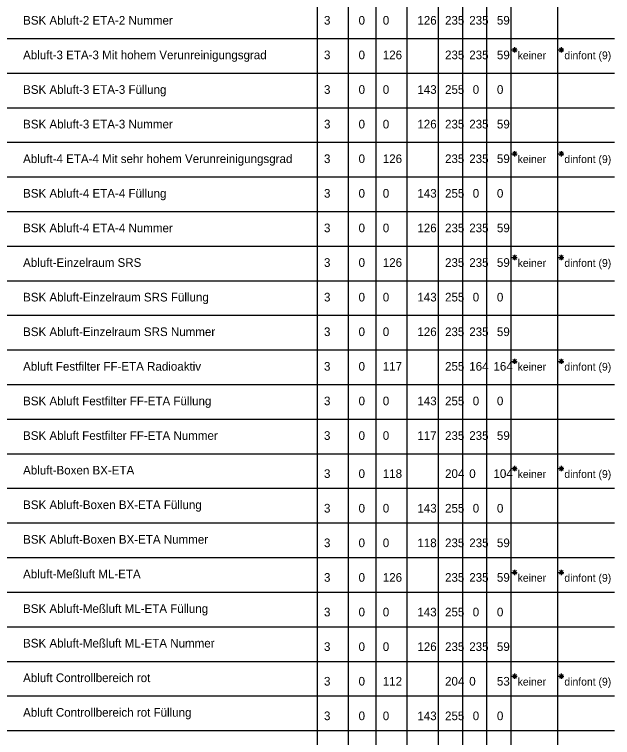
# Model space of a CAD drawing. Extents: x -12.9 to 27.6, y -77.8 to 7.2.
# Drawn here: x 8.13 to 16.77, y -35.1 to -24.65 of the extents above; entities that cross this region are included whole.
import ezdxf

# ---------------------------------------------------------------- set-up
doc = ezdxf.new("R2010")
doc.units = 0
doc.layers.add('Default', color=7, linetype='Continuous')

msp = doc.modelspace()

# ---------------------------------------------------------------- linework, layer by layer
at = {"layer": 'Default'}
for p, q in [((12.5, 0), (12.5, -73.5)), ((12.95, -0.35), (12.95, -59.5)), ((13.35, -0.35), (13.35, -59.5)), ((13.8, -0.35), (13.8, -59.5)), ((14.25, -0.35), (14.25, -59.5)), ((15.3, -0.35), (15.3, -59.5)), ((15.975, -0.35), (15.975, -59.5)), ((14.6, -0.75), (14.6, -59.5)), ((14.95, -0.75), (14.95, -59.5)), ((0, -25), (16.8, -25)), ((15.317, -25.165), (15.393, -25.165)), ((15.328, -25.138), (15.382, -25.192)), ((15.382, -25.138), (15.328, -25.192)), ((15.355, -25.127), (15.355, -25.203)), ((15.992, -25.165), (16.068, -25.165)), ((16.003, -25.138), (16.057, -25.192)), ((16.057, -25.138), (16.003, -25.192)), ((16.03, -25.127), (16.03, -25.203)), ((0, -25.5), (16.8, -25.5)), ((0, -26), (16.8, -26)), ((0, -26.5), (16.8, -26.5)), ((15.328, -26.638), (15.382, -26.692)), ((15.382, -26.638), (15.328, -26.692)), ((15.355, -26.627), (15.355, -26.703)), ((16.003, -26.638), (16.057, -26.692)), ((16.057, -26.638), (16.003, -26.692)), ((16.03, -26.627), (16.03, -26.703)), ((15.317, -26.665), (15.393, -26.665)), ((15.992, -26.665), (16.068, -26.665)), ((0, -27), (16.8, -27)), ((0, -27.5), (16.8, -27.5)), ((0, -28), (16.8, -28)), ((15.317, -28.165), (15.393, -28.165)), ((15.328, -28.138), (15.382, -28.192)), ((15.382, -28.138), (15.328, -28.192)), ((15.355, -28.127), (15.355, -28.203)), ((15.992, -28.165), (16.068, -28.165)), ((16.003, -28.138), (16.057, -28.192)), ((16.057, -28.138), (16.003, -28.192)), ((16.03, -28.127), (16.03, -28.203)), ((0, -28.5), (16.8, -28.5)), ((0, -29), (16.8, -29)), ((0, -29.5), (16.8, -29.5)), ((15.317, -29.665), (15.393, -29.665)), ((15.328, -29.638), (15.382, -29.692)), ((15.382, -29.638), (15.328, -29.692)), ((15.355, -29.627), (15.355, -29.703)), ((15.992, -29.665), (16.068, -29.665)), ((16.003, -29.638), (16.057, -29.692)), ((16.057, -29.638), (16.003, -29.692)), ((16.03, -29.627), (16.03, -29.703)), ((0, -30), (16.8, -30)), ((0, -30.5), (16.8, -30.5)), ((0, -31), (16.8, -31)), ((15.317, -31.215), (15.393, -31.215)), ((15.328, -31.188), (15.382, -31.242)), ((15.382, -31.188), (15.328, -31.242)), ((15.355, -31.177), (15.355, -31.253)), ((15.992, -31.215), (16.068, -31.215)), ((16.003, -31.188), (16.057, -31.242)), ((16.057, -31.188), (16.003, -31.242)), ((16.03, -31.177), (16.03, -31.253)), ((0, -31.5), (16.8, -31.5)), ((0, -32), (16.8, -32)), ((0, -32.5), (16.8, -32.5)), ((15.328, -32.688), (15.382, -32.742)), ((15.382, -32.688), (15.328, -32.742)), ((15.355, -32.677), (15.355, -32.753)), ((16.003, -32.688), (16.057, -32.742)), ((16.057, -32.688), (16.003, -32.742)), ((16.03, -32.677), (16.03, -32.753)), ((15.317, -32.715), (15.393, -32.715)), ((15.992, -32.715), (16.068, -32.715)), ((0, -33), (16.8, -33)), ((0, -33.5), (16.8, -33.5)), ((0, -34.001), (16.8, -34.001)), ((15.317, -34.215), (15.393, -34.215)), ((15.328, -34.188), (15.382, -34.242)), ((15.382, -34.188), (15.328, -34.242)), ((15.355, -34.177), (15.355, -34.253)), ((15.992, -34.215), (16.068, -34.215)), ((16.003, -34.188), (16.057, -34.242)), ((16.057, -34.188), (16.003, -34.242)), ((16.03, -34.177), (16.03, -34.253)), ((0, -34.5), (16.8, -34.5)), ((0, -35), (16.8, -35))]:
    msp.add_line(p, q, dxfattribs=at)

# ---------------------------------------------------------------- texts
for s, height, p in [('BSK Abluft-2 ETA-2 Nummer', 0.125, (8.25, -24.8)), ('3', 0.125, (12.6, -24.8)), ('0', 0.125, (13.1, -24.8)), ('0', 0.125, (13.45, -24.8)), ('126', 0.125, (13.95, -24.8)), ('235', 0.125, (14.35, -24.8)), ('235', 0.125, (14.7, -24.8)), ('59', 0.125, (15.1, -24.8)), ('Abluft-3 ETA-3 Mit hohem Verunreinigungsgrad', 0.125, (8.25, -25.3)), ('3', 0.125, (12.6, -25.3)), ('0', 0.125, (13.1, -25.3)), ('126', 0.125, (13.45, -25.3)), ('235', 0.125, (14.35, -25.3)), ('235', 0.125, (14.7, -25.3)), ('59', 0.125, (15.1, -25.3)), ('keiner', 0.1125, (15.4, -25.3)), ('dinfont (9)', 0.1125, (16.075, -25.3)), ('BSK Abluft-3 ETA-3 Füllung', 0.125, (8.25, -25.8)), ('3', 0.125, (12.6, -25.8)), ('0', 0.125, (13.1, -25.8)), ('0', 0.125, (13.45, -25.8)), ('143', 0.125, (13.95, -25.8)), ('255', 0.125, (14.35, -25.8)), ('0', 0.125, (14.75, -25.8)), ('0', 0.125, (15.1, -25.8)), ('BSK Abluft-3 ETA-3 Nummer', 0.125, (8.25, -26.3)), ('3', 0.125, (12.6, -26.3)), ('0', 0.125, (13.1, -26.3)), ('0', 0.125, (13.45, -26.3)), ('126', 0.125, (13.95, -26.3)), ('235', 0.125, (14.35, -26.3)), ('235', 0.125, (14.7, -26.3)), ('59', 0.125, (15.1, -26.3)), ('Abluft-4 ETA-4 Mit sehr hohem Verunreinigungsgrad', 0.125, (8.25, -26.8)), ('3', 0.125, (12.6, -26.8)), ('0', 0.125, (13.1, -26.8)), ('126', 0.125, (13.45, -26.8)), ('235', 0.125, (14.35, -26.8)), ('235', 0.125, (14.7, -26.8)), ('59', 0.125, (15.1, -26.8)), ('keiner', 0.1125, (15.4, -26.8)), ('dinfont (9)', 0.1125, (16.075, -26.8)), ('BSK Abluft-4 ETA-4 Füllung', 0.125, (8.25, -27.3)), ('3', 0.125, (12.6, -27.3)), ('0', 0.125, (13.1, -27.3)), ('0', 0.125, (13.45, -27.3)), ('143', 0.125, (13.95, -27.3)), ('255', 0.125, (14.35, -27.3)), ('0', 0.125, (14.75, -27.3)), ('0', 0.125, (15.1, -27.3)), ('BSK Abluft-4 ETA-4 Nummer', 0.125, (8.25, -27.8)), ('3', 0.125, (12.6, -27.8)), ('0', 0.125, (13.1, -27.8)), ('0', 0.125, (13.45, -27.8)), ('126', 0.125, (13.95, -27.8)), ('235', 0.125, (14.35, -27.8)), ('235', 0.125, (14.7, -27.8)), ('59', 0.125, (15.1, -27.8)), ('Abluft-Einzelraum SRS', 0.125, (8.25, -28.3)), ('3', 0.125, (12.6, -28.3)), ('0', 0.125, (13.1, -28.3)), ('126', 0.125, (13.45, -28.3)), ('235', 0.125, (14.35, -28.3)), ('235', 0.125, (14.7, -28.3)), ('59', 0.125, (15.1, -28.3)), ('keiner', 0.1125, (15.4, -28.3)), ('dinfont (9)', 0.1125, (16.075, -28.3)), ('BSK Abluft-Einzelraum SRS Füllung', 0.125, (8.25, -28.8)), ('3', 0.125, (12.6, -28.8)), ('0', 0.125, (13.1, -28.8)), ('0', 0.125, (13.45, -28.8)), ('143', 0.125, (13.95, -28.8)), ('255', 0.125, (14.35, -28.8)), ('0', 0.125, (14.75, -28.8)), ('0', 0.125, (15.1, -28.8)), ('BSK Abluft-Einzelraum SRS Nummer', 0.125, (8.25, -29.3)), ('3', 0.125, (12.6, -29.3)), ('0', 0.125, (13.1, -29.3)), ('0', 0.125, (13.45, -29.3)), ('126', 0.125, (13.95, -29.3)), ('235', 0.125, (14.35, -29.3)), ('235', 0.125, (14.7, -29.3)), ('59', 0.125, (15.1, -29.3)), ('Abluft Festfilter FF-ETA Radioaktiv ', 0.125, (8.25, -29.8)), ('3', 0.125, (12.6, -29.8)), ('0', 0.125, (13.1, -29.8)), ('117', 0.125, (13.45, -29.8)), ('255', 0.125, (14.35, -29.8)), ('164', 0.125, (14.7, -29.8)), ('164', 0.125, (15.05, -29.8)), ('keiner', 0.1125, (15.4, -29.8)), ('dinfont (9)', 0.1125, (16.075, -29.8)), ('BSK Abluft Festfilter FF-ETA Füllung', 0.125, (8.25, -30.3)), ('3', 0.125, (12.6, -30.3)), ('0', 0.125, (13.1, -30.3)), ('0', 0.125, (13.45, -30.3)), ('143', 0.125, (13.95, -30.3)), ('255', 0.125, (14.35, -30.3)), ('0', 0.125, (14.75, -30.3)), ('0', 0.125, (15.1, -30.3)), ('BSK Abluft Festfilter FF-ETA Nummer', 0.125, (8.25, -30.8)), ('3', 0.125, (12.6, -30.8)), ('0', 0.125, (13.1, -30.8)), ('0', 0.125, (13.45, -30.8)), ('117', 0.125, (13.95, -30.8)), ('235', 0.125, (14.35, -30.8)), ('235', 0.125, (14.7, -30.8)), ('59', 0.125, (15.1, -30.8)), ('Abluft-Boxen BX-ETA', 0.125, (8.25, -31.3)), ('3', 0.125, (12.6, -31.35)), ('0', 0.125, (13.1, -31.35)), ('118', 0.125, (13.45, -31.35)), ('204', 0.125, (14.35, -31.35)), ('0', 0.125, (14.7, -31.35)), ('104', 0.125, (15.05, -31.35)), ('keiner', 0.1125, (15.4, -31.35)), ('dinfont (9)', 0.1125, (16.075, -31.35)), ('BSK Abluft-Boxen BX-ETA Füllung', 0.125, (8.25, -31.8)), ('3', 0.125, (12.6, -31.85)), ('0', 0.125, (13.1, -31.85)), ('0', 0.125, (13.45, -31.85)), ('143', 0.125, (13.95, -31.85)), ('255', 0.125, (14.35, -31.85)), ('0', 0.125, (14.75, -31.85)), ('0', 0.125, (15.1, -31.85)), ('BSK Abluft-Boxen BX-ETA Nummer', 0.125, (8.25, -32.3)), ('3', 0.125, (12.6, -32.35)), ('0', 0.125, (13.1, -32.35)), ('0', 0.125, (13.45, -32.35)), ('118', 0.125, (13.95, -32.35)), ('235', 0.125, (14.35, -32.35)), ('235', 0.125, (14.7, -32.35)), ('59', 0.125, (15.1, -32.35)), ('Abluft-Meßluft ML-ETA', 0.125, (8.25, -32.8)), ('3', 0.125, (12.6, -32.85)), ('0', 0.125, (13.1, -32.85)), ('126', 0.125, (13.45, -32.85)), ('235', 0.125, (14.35, -32.85)), ('235', 0.125, (14.7, -32.85)), ('59', 0.125, (15.1, -32.85)), ('keiner', 0.1125, (15.4, -32.85)), ('dinfont (9)', 0.1125, (16.075, -32.85)), ('BSK Abluft-Meßluft ML-ETA Füllung', 0.125, (8.25, -33.3)), ('3', 0.125, (12.6, -33.35)), ('0', 0.125, (13.1, -33.35)), ('0', 0.125, (13.45, -33.35)), ('143', 0.125, (13.95, -33.35)), ('255', 0.125, (14.35, -33.35)), ('0', 0.125, (14.75, -33.35)), ('0', 0.125, (15.1, -33.35)), ('BSK Abluft-Meßluft ML-ETA Nummer', 0.125, (8.25, -33.8)), ('3', 0.125, (12.6, -33.85)), ('0', 0.125, (13.1, -33.85)), ('0', 0.125, (13.45, -33.85)), ('126', 0.125, (13.95, -33.85)), ('235', 0.125, (14.35, -33.85)), ('235', 0.125, (14.7, -33.85)), ('59', 0.125, (15.1, -33.85)), ('Abluft Controllbereich rot', 0.125, (8.25, -34.3)), ('3', 0.125, (12.6, -34.35)), ('0', 0.125, (13.1, -34.35)), ('112', 0.125, (13.45, -34.35)), ('204', 0.125, (14.35, -34.35)), ('0', 0.125, (14.7, -34.35)), ('53', 0.125, (15.1, -34.35)), ('keiner', 0.1125, (15.4, -34.35)), ('dinfont (9)', 0.1125, (16.075, -34.35)), ('Abluft Controllbereich rot Füllung', 0.125, (8.25, -34.8)), ('3', 0.125, (12.6, -34.85)), ('0', 0.125, (13.1, -34.85)), ('0', 0.125, (13.45, -34.85)), ('143', 0.125, (13.95, -34.85)), ('255', 0.125, (14.35, -34.85)), ('0', 0.125, (14.75, -34.85)), ('0', 0.125, (15.1, -34.85))]:
    msp.add_text(s, height=height, dxfattribs=at).set_placement(p)

doc.saveas('drawing.dxf')
